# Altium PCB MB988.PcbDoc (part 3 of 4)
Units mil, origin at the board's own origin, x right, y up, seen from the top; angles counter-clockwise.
Board outline 4505 x 6805 mil, 4 copper layers (TopLayer, VCC, GND, BottomLayer), stack 71.6 mil thick; 546 components, 390 nets, 1907 pads, 809 vias.
Unrouted connection lines stored in the file: 2.
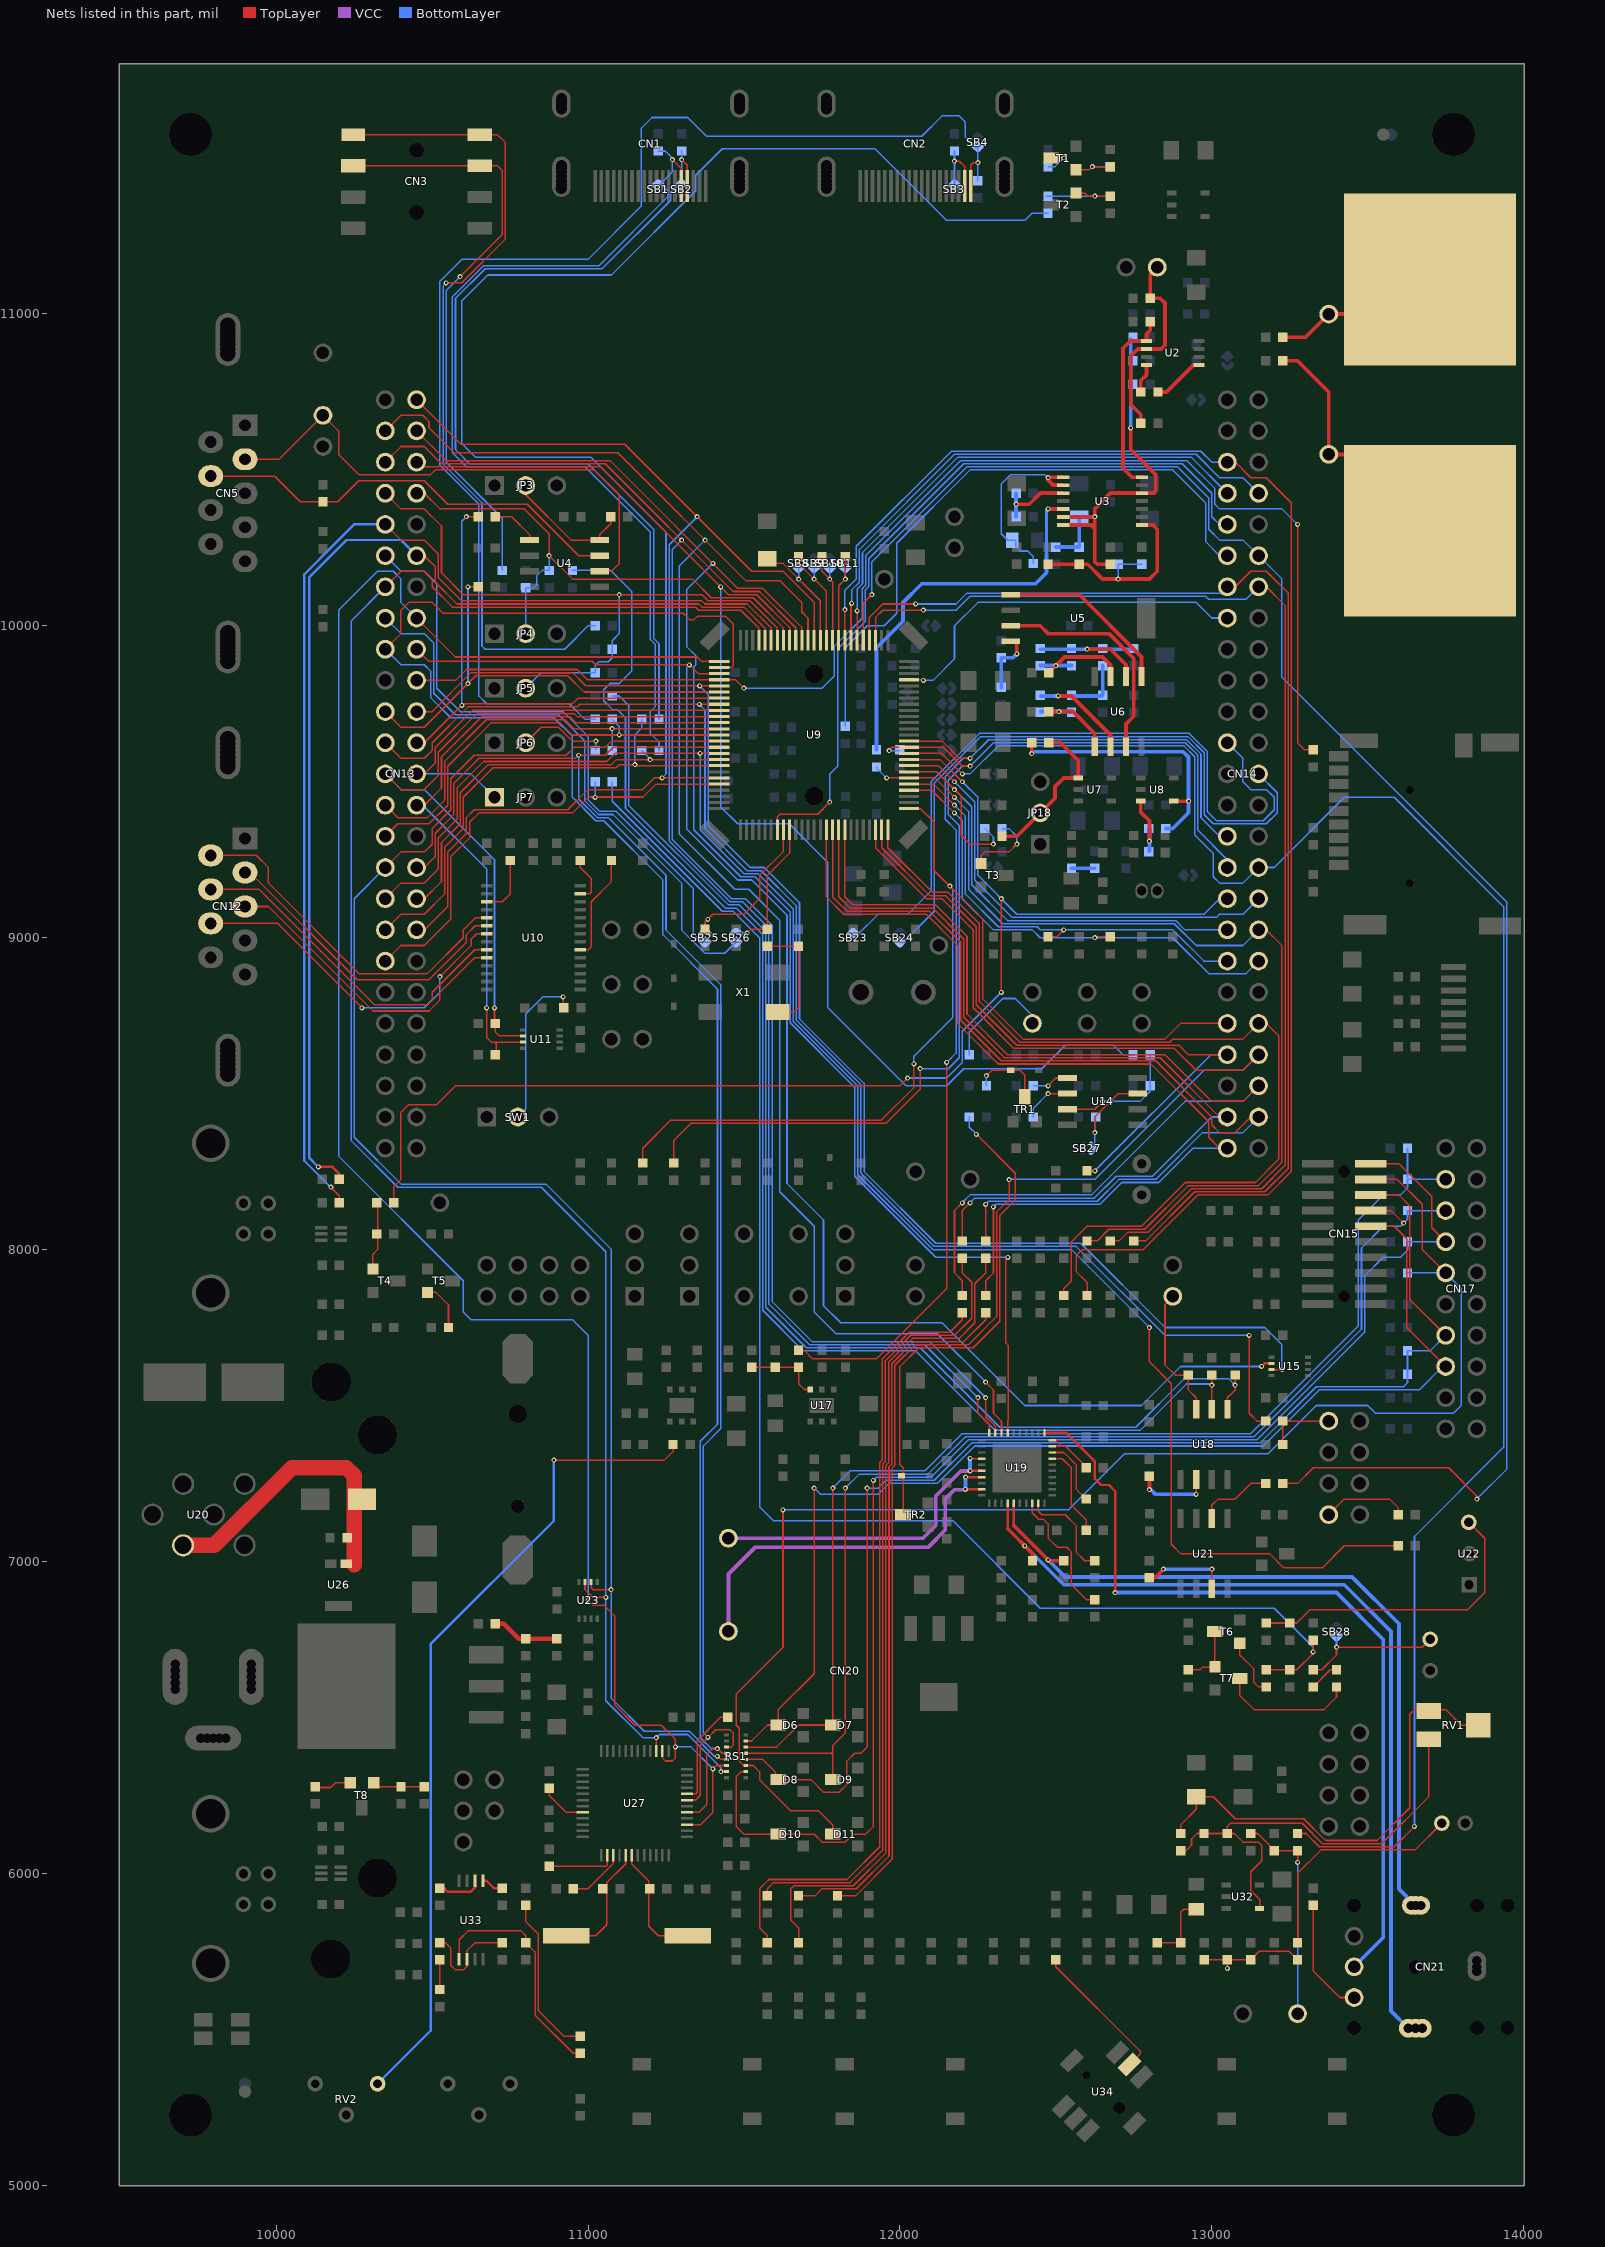
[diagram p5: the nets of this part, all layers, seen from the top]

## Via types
v1: diameter 16, hole 8, TopLayer to BottomLayer, tented both sides, 786 vias
v2: diameter 25, hole 16, TopLayer to BottomLayer, tented both sides, 20 vias
v3: diameter 50, hole 28, TopLayer to BottomLayer, tented both sides, 3 vias

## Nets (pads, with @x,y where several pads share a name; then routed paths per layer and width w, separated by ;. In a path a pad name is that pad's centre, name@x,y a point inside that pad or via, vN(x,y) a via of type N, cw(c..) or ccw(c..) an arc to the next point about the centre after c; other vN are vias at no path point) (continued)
NetR120_2: R120.2 T1.3 | length 101.6
  TopLayer w5: T1.3@12485,11500.5 12524.5,11500.5 v1(12525,11500)
  BottomLayer w5: R120.2@12475,11472.5 12497.5,11472.5 v1(12525,11500)
NetR122_1: R122.1 T6.3 T7.2 | length 202.1
  TopLayer w5: R122.1@12925,6652.5 12962.5,6652.5 12970,6660 13007.5,6660 T7.2@13010,6662.5 T6.3@13010,6775.5
NetR123_2: R123.2 T6.2 | length 189.9
  TopLayer w5: T6.2@13090,6737.5 13090,6700 13135,6655 13135,6612.5 13150,6597.5 R123.2@13175,6597.5
NetR125_1: R125.1 T7.3 | length 432.2
  TopLayer w5: T7.3@13090,6624.5 13090,6570 13135,6525 13360,6525 13400,6565 R125.1@13400,6597.5
NetR125_2: R125.2 R240.1 | length 97.8
  TopLayer w5: R240.1@13325,6597.5 13380,6652.5 R125.2@13400,6652.5
NetR128_1: R128.1 T8.1 | length 116.2
  TopLayer w5: R128.1@10127.5,6275 10175,6275 10190,6290 T8.1@10237.5,6290
NetR129_1: R129.1 U21.6 | length 244
  TopLayer w5: U21.6@13000,7137.5 13000,7180 13020,7200 13075,7200 13125,7250 R129.1@13172.5,7250
NetR131_2: R131.2 R132.1 T8.2 | length 162.5
  TopLayer w5: T8.2@10312.5,6277.5 R132.1@10475,6277.5
NetR137_2: R137.2 U27.2 | length 219.3
  TopLayer w5: R137.2@10875,6022.5 11057.5,6022.5 11061.42,6026.42 U27.2@11061.42,6057.68
NetR139_1: CN1.15 R139.1 R173.1 SB1.1 | length 3087.5
  TopLayer w5: v1(11270,11495) 11298.43,11466.57 CN1.15@11298.43,11410
  BottomLayer w5: R173.1@11225,11522.5 11247.5,11522.5 11270,11500 11270,11455 SB1.1@11233,11418 11255,11396 11255,11375 11035,11155 10665,11155 10565,11055 10565,10555 10610,10510 10990,10510 11200,10300 11200,9955.86 11215,9940.86 11215,9740 11200,9725 11200,9655 11227.5,9627.5 R139.1@11227.5,9600
NetR140_1: C72.1 R140.1 R141.2 RV1.1 U32.4 | length 1457
  TopLayer w5: R140.1@12900,6072.5 12917.5,6072.5 12935,6090 12935,6110 12952.5,6127.5 R141.2@12975,6127.5 ; R141.2@12977.5,6127.5 13072.5,6127.5 13100,6100 13150,6100 13160,6090 13160,6040 13125,6005 13125,5945 13153.15,5916.85 U32.4@13153.15,5887.6 ; C72.1@13050,6127.5 13050,6150 13060,6160 13290,6160 13355,6095 13545,6095 13696.26,6246.26 RV1.1@13696.26,6404.72
NetR140_2: C71.1 R140.2 RV1.2 RV1.3 | length 1470.4
  TopLayer w5: R140.2@12900,6127.5 12900,6155 12950,6205 C71.1@12950,6245 13005,6245 13075,6175 13295,6175 13365,6105 13530,6105 13635,6210 13635,6510 13650,6525 13750,6525 13800,6475 RV1.2@13853.74,6475
NetR144_1: LD5.2 R144.1 | length 523.2
  TopLayer w5: R144.1@10800,5897.5 10800,5845 10840,5805 10840,5560 10922.5,5477.5 LD5.2@10975,5477.5
NetR145_2: R145.2 U27.3 | length 188.8
  TopLayer w5: R145.2@10952.5,5950 11000,5950 11081.1,6031.1 U27.3@11081.1,6057.68
NetR146_1: R77.2 R146.1 | length 2554.3
  TopLayer w5: R146.1@11575,5927.5 11575,5950 11595,5970 11840,5970 11945,6075 11945,7312.22 11953.64,7320.86 11953.64,7643.64 12035,7725 12175,7725 12230,7780 12230,7895 12200,7925 R77.2@12200,7972.5
NetR147_1: R88.2 R147.1 | length 2307.4
  TopLayer w5: R147.1@11675,5927.5 11727.5,5927.5 11750,5950 11860,5950 11965,6055 11965,7303.93 11973.64,7312.57 11973.64,7633.64 12045,7705 12205,7705 12275,7775 R88.2@12275,7797.5
NetR148_1: CN1.16 R148.1 R172.1 SB2.1 | length 2927.5
  TopLayer w5: v1(11300,11495) 11318.11,11476.89 CN1.16@11318.11,11410
  BottomLayer w5: R148.1@11227.5,9700 11227.5,9942.5 11210,9960 11210,10310 11000,10520 10620,10520 10575,10565 10575,11050 10670,11145 11045,11145 11265,11365 11265,11391 SB2.1@11292,11418 ; SB2.1@11300,11415 R172.1@11300,11522.5
NetR156_1: R87.2 R156.1 | length 2522.2
  TopLayer w5: R156.1@11575,5777.5 11575,5800 11550,5825 11550,5950 11580,5980 11830,5980 11935,6085 11935,7316.36 11943.64,7325 11943.64,7648.64 12030,7735 12160,7735 12200,7775 R87.2@12200,7797.5
NetR157_1: R78.2 R157.1 | length 2663.4
  TopLayer w5: R157.1@11675,5777.5 11675,5825 11650,5850 11650,5950 11660,5960 11850,5960 11955,6065 11955,7308.07 11963.64,7316.72 11963.64,7638.64 12040,7715 12190,7715 12240,7765 12240,7890 12275,7925 R78.2@12275,7972.5
NetR159_1: R2.1 R159.1 T2.1 | length 271.6
  TopLayer w5: T2.1@12565,11387.5 12592.5,11387.5 12602.5,11377.5 R2.1@12675,11377.5
  BottomLayer w5: R159.1@12467.5,11377.5 v1(12625,11377.5)
NetR162_2: R162.2 U34.5 | length 462
  TopLayer w5: R162.2@12500,5722.5 12500,5700 12770,5430 12770,5420 U34.5@12736.3,5386.3
NetR163_1: CN20.1 R110.1 R163.1 | length 222.5
  TopLayer w5: R110.1@13227.5,7375 R163.1@13227.5,7450 CN20.1@13375,7450
NetR165_1: C89.1 C135.1 R164.1 R165.1 | length 350
  TopLayer w5: C89.1@12975.28,5722.44 13124.94,5722.44 13152.5,5750 13247.5,5750 R165.1@13275,5722.5 ; v1(13050,5695) R164.1@13050,5722.5
NetR166_2: CN21.6 R166.2 | length 377.4
  TopLayer w5: R166.2@13325,5897.5 13325,5686.57 13410,5601.57 CN21.6@13456.3,5601.57
NetR171_2: C81.1 R170.1 R171.2 | length 226.6
  TopLayer w5: R171.2@12825,5777.5 R170.1@12900,5777.5 12900,5875 12910,5885 C81.1@12950,5885
NetR176_2: R1.2 R176.2 T1.2 | length 171.6
  TopLayer w5: T1.2@12565,11462.5 12607.5,11462.5 v1(12617.5,11472.5) R1.2@12675,11472.5
  BottomLayer w5: v1(12617.5,11472.5) R176.2@12675,11472.5
NetR178_1: C94.1 C97.2 R18.1 R177.1 R178.1 R180.1 R188.2 U3.5 U3.13 U3.14 | length 1409.7
  TopLayer w5: 12623.23,10323.23 12625,10325 ; v1@12623.82,10348.82 v1(12625,10350)
  TopLayer w12: U3.14@12524.02,10323.23 12623.23,10323.23 ; U3.13@12524.02,10348.82 v1@12623.82,10348.82 ; 12610,10323.23 12611.77,10323.23 12625,10310 ; R18.1@12675,10197.5 12632.5,10197.5 12625,10205 12625,10375 12675.59,10425.59 12815.59,10425.59 12820,10430 12820,10485 12740,10565 v1(12740,10635)
  BottomLayer w12: R188.2@12500,10252.5 12574.65,10252.5 C97.2@12574.72,10252.44 C94.1@12574.72,10344.72 ; C94.1@12570,10350 v1(12625,10350) ; v1(12740,10635) R177.1@12740,10920
NetR181_1: C92.2 R181.1 U3.10 | length 241.3
  TopLayer w12: v1(12372.5,10390) 12415,10390 12450.59,10425.59 U3.10@12524.02,10425.59
  BottomLayer w12: R181.1@12372.5,10350 C92.2@12372.5,10425
NetR182_1: JP3.2 R182.1 U4.8 | length 417.1
  TopLayer w5: JP3.2@10800,10450 10800,10420 10945,10275 U4.8@11037.5,10275 11037.5,10292.5 11072.5,10327.5 R182.1@11072.5,10350
NetR185_2: CN3.2 R185.2 | length 1915.3
  TopLayer w5: CN3.2@10247.5,11475 10710,11475 10725,11460 10725,11255 v1(10590,11120)
  BottomLayer w5: v1(10590,11120) 10545,11075 10545,10525 10725,10345 R185.2@10725,10177.5
NetR190_2: CN3.1 R190.2 | length 2674.5
  TopLayer w5: CN3.1@10247.5,11575 10710,11575 10735,11550 10735,11240 10595,11100 v1(10545,11100)
  BottomLayer w5: v1(10545,11100) 10535,11090 10535,10519.14 10660,10394.14 10660,9935 10670,9925 10925,9925 11000,10000 R190.2@11022.5,10000
NetR193_2: C101.2 R21.2 R193.2 U6.7 | length 366.1
  TopLayer w12: R21.2@12477.5,9850 12527.5,9900 12650,9900 12675,9875 U6.7@12675,9837.5
  BottomLayer w12: C101.2@12450,9872.5 R193.2@12550,9872.5
  other v1: 12500,9872.5
NetR194_1: C101.1 R193.1 R194.1 R198.1 U6.6 | length 480.7
  TopLayer w12: v1(12600,9925) 12675,9925 12725,9875 U6.6@12725,9837.5
  BottomLayer w12: C101.1@12450,9925 R198.1@12747.5,9925
NetR194_2: C104.1 R194.2 R200.1 R205.2 U6.2 | length 546.8
  TopLayer w12: v1(12507.5,9775) 12550,9775 12675,9650 U6.2@12675,9612.5
  BottomLayer w12: C104.1@12452.5,9775 R205.2@12647.5,9775 ; R205.2@12650,9777.5 R194.2@12650,9872.5
NetR197_2: R196.2 R197.2 U5.1 | length 190.2
  TopLayer w12: v1(12375,9910) U5.1@12375,9950
  BottomLayer w12: R197.2@12325,9802.5 R196.2@12325,9897.5 12362.5,9897.5 v1(12375,9910)
NetR199_2: JP6.2 R199.2 | length 291.9
  TopLayer w5: JP6.2@10800,9625 10850,9675 10905,9675 10950,9630 v1(11025,9630)
  BottomLayer w5: R199.2@11025,9602.5 v1(11025,9630)
NetR200_2: C104.2 R23.2 R200.2 U6.1 | length 314
  TopLayer w12: R23.2@12477.5,9725 12555,9725 12625,9655 U6.1@12625,9612.5
  BottomLayer w12: C104.2@12452.5,9725 R200.2@12547.5,9725
  other v1: 12510,9725
NetR203_1: CN14.11 R203.1 | length 2032.5
  BottomLayer w5: R203.1@11825,9677.5 11825,9930 11895,10000 11950,10000 11990,10040 11990,10265 12225,10500 12875,10500 12980,10395 12980,10270 13025,10225 CN14.11@13050,10225
NetR204_2: R33.1 R204.2 U8.4 | length 867.3
  TopLayer w12: v1(12422.5,9590) R33.1@12422.5,9625 ; U8.4@12878.15,9437.6 v1(12925.4,9437.6)
  BottomLayer w12: v1(12422.5,9590) 12429,9596.5 12907.91,9596.5 12925,9579.41 v1@12925,9437.6 ; R204.2@12852.5,9350 12875,9350 12925.4,9400.4 v1(12925.4,9437.6)
NetR208_2: R204.1 R208.2 U8.3 | length 209.3
  TopLayer w12: U8.3@12771.85,9437.6 12771.85,9403.15 12800,9375 v1(12800,9310)
  BottomLayer w12: R208.2@12800,9277.5 R204.1@12800,9347.5
NetR209_2: R207.1 R209.2 | length 75
  BottomLayer w12: R207.1@12550,9222.5 R209.2@12625,9222.5
NetR211_2: R211.2 U10.20 | length 343.3
  TopLayer w5: U10.20@10974.61,8961.61 11001.61,8961.61 11010,8970 11010,9115 11075,9180 R211.2@11075,9247.5
NetR212_2: CN9.2 R212.2 | length 370.8
  BottomLayer w5: R212.2@12222.5,8625 12222.5,8697.5 12330,8805 12370,8805 12425,8750 CN9.2@12425,8725 CN9.2@12427.5,8722.5
NetR215_1: R214.1 R215.1 U14.3 | length 406.3
  TopLayer w5: U14.3@12537.5,8450 12625,8450 v1(12650,8475)
  BottomLayer w5: v1(12650,8475) 12770,8475 12802.5,8507.5 R215.1@12802.5,8625
NetR216_2: R216.2 SW1.2 | length 519.2
  TopLayer w5: v1(10920,8810) 10920,8777.5 R216.2@10922.5,8775
  BottomLayer w5: SW1.2@10775,8425 10800,8450 10800,8755 10855,8810 v1(10920,8810)
NetR217_2: D3.2 R217.2 TR1.3 | length 238.7
  TopLayer w5: v1(12277.5,8557.5) 12295,8575 12385,8575 12400.5,8559.5 TR1.3@12400.5,8490
  BottomLayer w5: R217.2@12277.5,8525 v1(12277.5,8557.5)
NetR218_2: R218.2 U14.1 | length 120.4
  TopLayer w5: v1(12475,8525) 12500,8550 U14.1@12537.5,8550
  BottomLayer w5: R218.2@12427.5,8525 v1(12475,8525)
NetR220_2: D5.2 R220.2 TR2.3 | length 1595.5
  TopLayer w5: TR2.3@12010,7150.5 12010,7300 12000,7310 12000,7625 12060,7685 12235,7685 12320,7770 12320,8109.14 12370,8159.14 12370,8245 v1(12245.5,8369.5)
  BottomLayer w5: R220.2@12222.5,8425 12222.5,8392.5 v1(12245.5,8369.5)
NetR222_2: R222.2 U14.2 | length 157.2
  TopLayer w5: v1(12475,8500) U14.2@12537.5,8500
  BottomLayer w5: R222.2@12427.5,8425 12427.5,8452.5 v1(12475,8500)
NetR235_2: R235.2 U18.2 | length 261.2
  TopLayer w5: v1(12950,7215) U18.2@12950,7277.5
  TopLayer w12: v1(12800,7230) R235.2@12800,7272.5
  BottomLayer w12: v1(12800,7230) 12805,7230 12820,7215 v1(12950,7215)
NetR237_2: L4.1 R237.2 R238.2 | length 217.2
  TopLayer w15: L4.1@10702.5,6800 10730,6800 10777.5,6752.5 R237.2@10900,6752.5
NetR240_2: LD10.2 R240.2 SB28.2 | length 467
  TopLayer w5: R240.2@13325,6652.5 13352.5,6652.5 13400,6700 v1(13400,6725) 13675,6725 LD10.2@13700,6750
  BottomLayer w5: v1(13400,6725) SB28.2@13400,6762
NetR242_1: R242.1 U33.6 | length 145.2
  TopLayer w8: R242.1@10525,5952.5 10537.5,5952.5 10550,5940 10622.8,5940 10637.8,5955 U33.6@10637.8,5975.98
NetR243_1: R243.1 U33.5 | length 71.3
  TopLayer w8: U33.5@10663.39,5975.98 10674.02,5975.98 10697.5,5952.5 R243.1@10725,5952.5
NetR244_1: R244.1 R246.2 U33.2 | length 334
  TopLayer w5: R246.2@10525,5777.5 10542.5,5777.5 10560,5760 10560,5705 10575,5690 10600,5690 10612.21,5702.21 10612.21,5752.21 10637.21,5777.21 10724.71,5777.21 R244.1@10725,5777.5
NetR246_1: R160.2 R246.1 | length 95
  TopLayer w5: R160.2@10525,5627.5 R246.1@10525,5722.5
NetR247_1: CN20.7 R247.1 | length 277.1
  TopLayer w5: CN20.7@13375,7150 13425,7200 13570,7200 13597.5,7172.5 R247.1@13597.5,7150
NetR248_1: R248.1 U4.1 | length 151.3
  TopLayer w5: R248.1@10702.5,10350 10755,10350 10812.5,10292.5 U4.1@10812.5,10275
NetR249_1: R119.2 R123.1 R124.2 R249.1 | length 4731.9
  TopLayer w5: R123.1@13175,6652.5 13272.5,6652.5 13325,6705 R119.2@13325,6747.5
  BottomLayer w5: R249.1@11077.5,9500 11077.5,9437.5 11430,9085 11465,9085 11550,9000 11550,7175 11595,7130 12170,7130 12450,6850 13200,6850 13325,6725 v1(13325,6710)
NetRS1_4: CN15.10 CN17.15 D6.3 RS1.4 | length 3718.8
  TopLayer w5: RS1.4@11506,6424.21 11524.21,6424.21 11575.5,6475.5 D6.3@11610,6475.5 11610,6525 11725,6640 v1(11725,7235) ; CN15.10@13510,8075 13585,8075 13625,8035 13625,7750 CN17.15@13750,7625
  BottomLayer w5: v1(11725,7235) 11745,7215 11930,7215 11965,7250 12120,7250 12240,7370 13165,7370 13345,7550 13665,7550 CN17.15@13740,7625
NetRS1_6: CN17.3 D7.3 R223.2 R224.1 RS1.6 | length 3750.7
  TopLayer w5: RS1.6@11506,6404.53 11604.53,6404.53 11675.5,6475.5 D7.3@11785,6475.5 v1(11785,7235)
  BottomLayer w5: v1(11785,7235) 11840,7290 12080,7290 12200,7410 13125,7410 13470,7755 13470,8095 13550,8175 13605,8175 13627.5,8197.5 R223.2@13627.5,8225 CN17.3@13750,8225 ; R223.2@13627.5,8232.5 R224.1@13627.5,8325
NetRS1_8: CN15.8 CN17.5 D9.3 R225.1 RS1.8 | length 3827.7
  TopLayer w5: RS1.8@11506,6384.84 11784.84,6384.84 ; 11784.68,6380 11779.84,6384.84 11785,6390 ; D9.3@11785,6300.5 11785,6410 11825,6450 v1(11825,7235) ; CN15.8@13510,8125 13575,8125 v1(13615,8085)
  BottomLayer w5: v1(11825,7235) 11870,7280 12090,7280 12210,7400 13135,7400 13480,7745 13480,8005 13550,8075 13605,8075 13627.5,8097.5 R225.1@13627.5,8125 CN17.5@13750,8125
NetRS1_10: CN15.6 CN17.13 D8.3 R230.2 R231.1 RS1.10 | length 4096.5
  TopLayer w5: RS1.10@11506,6365.16 11559.84,6365.16 11600,6325 D8.3@11600,6295 ; D8.3@11610,6300.5 11714.5,6300.5 11755,6260 11805,6260 11830,6285 11830,6360 11855,6385 11875,6385 11895,6405 v1(11895,7235) ; CN15.6@13510,8175 13600,8175 13635,8140 13635,7840 CN17.13@13750,7725
  BottomLayer w5: v1(11895,7235) 11930,7235 11955,7260 12110,7260 12230,7380 13155,7380 13335,7560 13615,7560 13627.5,7572.5 R231.1@13627.5,7675 13700,7675 CN17.13@13750,7725
NetRS1_12: CN15.4 CN17.9 D11.3 R226.2 RS1.12 | length 4652.2
  TopLayer w5: v1(11625,7165) 11625,6725 11475,6575 11475,6475 11485,6465 11485,6360 11499.53,6345.47 11529.53,6345.47 11550,6325 11550,6300 11650,6200 11740,6200 11785,6155 D11.3@11785,6125.5 ; CN15.4@13510,8225 13595,8225 13675,8145 13675,8000 CN17.9@13750,7925
  BottomLayer w5: v1(11625,7165) 12540,7165 12720,7345 13180,7345 13335,7500 13500,7500 13525,7475 13775,7475 13800,7500 13800,7875 CN17.9@13750,7925 R226.2@13627.5,7925
NetRS1_14: CN15.2 CN17.7 D10.3 R227.1 RS1.14 | length 4464.5
  TopLayer w5: RS1.14@11506,6325.79 11490.79,6325.79 11475,6310 11475,6150 11500,6125 11725,6125 11750,6100 11825,6100 11850,6125 11890,6125 11915,6150 v1(11915,7260) ; CN15.2@13510,8275 13600,8275 13705,8170 13705,8070 CN17.7@13750,8025
  BottomLayer w5: v1(11915,7260) 11925,7270 12100,7270 12220,7390 13145,7390 13490,7735 13490,7915 13550,7975 13605,7975 13627.5,7997.5 R227.1@13627.5,8025 CN17.7@13750,8025
NetRV2_1: R107.2 RV2.1 | length 2650.4
  TopLayer w5: v1(10890,7325) 11245,7325 11272.5,7352.5 R107.2@11272.5,7375
  BottomLayer w8: RV2.1@10325,5325 10495,5495 10495,6735 10890,7130 v1(10890,7325)
NetSB3_2: CN2.18 R174.2 SB3.2 | length 206.7
  TopLayer w5: v1(12175,11490) 12190,11490 12207.48,11472.52 CN2.18@12207.48,11410
  BottomLayer w5: SB3.2@12175,11418 R174.2@12175,11522.5
NetSB4_2: CN2.19 R135.2 R175.2 SB4.2 | length 4196.6
  TopLayer w5: CN2.19@12227.17,11410 12227.17,11477.17 12235,11485 v1(12250,11485)
  BottomLayer w5: R135.2@11022.5,9700 10990,9700 10940,9750 10675,9750 10650,9775 10650,10390 10525,10515 10525,11105 10595,11175 11000,11175 11170,11345 11170,11595 11205,11630 11320,11630 11380,11570 12070,11570 12135,11635 12190,11635 12210,11615 12210,11567 12245,11532 SB4.2@12243,11532 ; R175.2@12250,11427.5 SB4.2@12250,11537
NetSB23_2: CN14.23 SB23.2 | length 2356.9
  BottomLayer w5: SB23.2@11865,9010 11929.52,9074.52 12024.52,9074.52 12100,9150 12100,9500 12255,9655 12927.57,9655 12985.46,9597.11 12985.46,9404.54 13015,9375 13165,9375 13200,9410 13200,9450 13175,9475 13125,9475 13100,9500 13100,9575 CN14.23@13050,9625
NetSB24_2: CN14.26 SB24.2 | length 2114.9
  BottomLayer w5: SB24.2@12007,8982 12110,9085 12110,9495.86 12259.14,9645 12923.43,9645 12975.46,9592.97 12975.46,9394.54 13005,9365 13175,9365 13210,9400 13210,9465 CN14.26@13150,9525
NetSB25_2: CN13.11 SB25.2 | length 1932.7
  BottomLayer w5: CN13.11@10350,10225 10400,10175 10475,10175 10515,10135 10515,9800 10590,9725 10920,9725 11000,9645 11000,9442.43 11037.43,9405 11090,9405 11338,9157 11338,9012 SB25.2@11368,8982
NetSB26_2: CN13.15 SB26.2 | length 1880
  BottomLayer w5: CN13.15@10350,10025 10400,9975 10475,9975 10505,9945 10505,9784.14 10574.14,9715 10905,9715 10990,9630 10990,9438.28 11033.28,9395 11080,9395 11300,9175 11300,9025 11375,8950 11438,8950 SB26.2@11475,8987
NetT3_2: R22.1 T3.2 | length 238.4
  TopLayer w5: T3.2@12260,9237.5 12260,9262.5 12272.5,9275 12350,9275 v1(12375,9300)
  BottomLayer w5: R22.1@12327.5,9350 12350,9350 12375,9325 v1(12375,9300)
NetT4_2: R51.1 R65.1 T4.2 | length 216.2
  TopLayer w5: T4.2@10310,7937.5 10310,7985 10325,8000 R51.1@10325,8147.5
NetT5_1: R84.1 T5.1 | length 156.6
  TopLayer w5: T5.1@10485,7862.5 10512.5,7862.5 10552.5,7822.5 R84.1@10552.5,7750
NetTP16_1: C79.1 R136.2 R241.1 TP16.1 | length 696.7
  TopLayer w5: R241.1@13125,6127.5 13147.5,6127.5 13200,6075 C79.1@13200,6072.5 R136.2@13275,6072.5 v1(13275,6035)
  BottomLayer w5: TP16.1@13275,5550 v1(13275,6035)
NetTS1_1: R4.1 TP1.1 TS1.1 | length 453.6
  TopLayer w12: R4.1@13227.5,10925 13300,10925 13375,11000 TS1.1@13650,11000
NetTS2_1: R20.1 TP3.1 TS2.1 | length 624.2
  TopLayer w12: R20.1@13227.5,10850 13275,10850 13375,10750 TP3.1@13375,10549.72 TS2.1@13610,10549.72
NetU2_1: R5.2 U2.1 | length 168.2
  TopLayer w12: R5.2@12827.44,10749.72 12854.72,10749.72 12941.61,10836.61 U2.1@12959.69,10836.61
NetU2_5: C2.1 U2.5 U3.7 | length 609.6
  TopLayer w12: U3.7@12775.98,10476.77 12743.23,10476.77 12715,10505 12715,10890 12738.39,10913.39 U2.5@12790.31,10913.39 12790.31,10935.31 12802.56,10947.56 C2.1@12802.56,10975.28
NetU2_6: JP1.2 R3.2 R6.1 U2.6 | length 651
  TopLayer w12: R6.1@12772.5,10650 12772.5,10677.5 12740,10710 12740,10865 12762.8,10887.8 12837.8,10887.8 12850,10900 12850,11035 12835,11050 R3.2@12802.5,11050 12802.5,11127.5 JP1.2@12825,11150
NetU2_8: R5.1 U2.8 | length 94.3
  TopLayer w12: R5.1@12772.44,10749.72 12772.44,10786.82 12790.31,10804.69 U2.8@12790.31,10836.61
NetU3_1: C98.1 R16.1 R17.1 R184.2 U3.1 | length 692
  TopLayer w12: R16.1@12475,10197.5 12602.5,10197.5 12650,10150 12800,10150 12825,10175 12825,10310 12811.77,10323.23 U3.1@12775.98,10323.23
  BottomLayer w5: v1(12700,10150) C98.1@12700,10197.5 R184.2@12775,10197.5
NetU3_9: C96.2 R183.2 U3.8 U3.9 | length 607.4
  TopLayer w12: U3.9@12524.02,10451.18 12491.18,10451.18 12475,10467.36 v1(12475,10475) 12476.77,10476.77 U3.8@12524.02,10476.77
  BottomLayer w5: R183.2@12427.5,10200 12427.5,10222.5 12410,10240 12385,10240 12372.12,10252.88 12372.12,10274.5 12345.5,10274.5 12325,10295 12325,10455 12355,10485 12465,10485 v1(12475,10475)
NetU3_12: R201.2 U3.12 | length 1263.4
  TopLayer w5: v1(12475,10375) v1@12475.59,10374.41
  TopLayer w12: v1@12475.59,10374.41 U3.12@12524.02,10374.41
  BottomLayer w10: 12470,10230 12470,10370 v1(12475,10375)
  BottomLayer w12: R201.2@11925,9602.5 11925,9930 12010,10015 12010,10075 12070,10135 12435,10135 12470,10170 12470,10230
NetU4_6: CN5.2 JP2.2 U4.6 | length 1713.2
  TopLayer w5: CN5.2@9900,10534 10009,10534 JP2.2@10150,10675 10200,10625 10200,10550 10265,10485 10495,10485 10510,10500 11020,10500 11100,10420 11100,10200 11075,10175 U4.6@11037.5,10175
NetU4_7: CN5.7 R7.1 U4.7 | length 1409
  TopLayer w5: CN5.7@9790,10480 9995,10480 10077.5,10397.5 10197.5,10397.5 10265,10465 10475,10465 10550,10390 10805,10390 10970,10225 U4.7@11037.5,10225
NetU5_2: U5.2 U6.3 | length 731.3
  TopLayer w12: U5.2@12355,10000 12450,10000 12475,9975 12670,9975 12750,9895 12750,9710 12725,9685 U6.3@12725,9612.5
NetU5_4: U5.4 U6.5 | length 565.3
  TopLayer w12: U5.4@12355,10100 12575,10100 12775,9900 U6.5@12775,9837.5
NetU7_1: JP18.2 R33.2 R34.2 U7.1 | length 517.5
  TopLayer w12: R34.2@12327.5,9325 12375,9325 12497.4,9447.4 12497.4,9484.8 12525,9512.4 U7.1@12571.85,9512.4 12571.85,9568.15 12515,9625 R33.2@12477.5,9625
NetU10_3: C15.1 U10.3 | length 192.4
  TopLayer w5: U10.3@10675.39,9115.16 10725,9115.16 10750.28,9140.44 C15.1@10750.28,9247.44
NetU10_5: CN12.6 U10.5 | length 1160.4
  TopLayer w5: CN12.6@9790,9264 9936,9264 9975,9225 9975,9175 10265,8885 10485,8885 10600,9000 10600,9025 10638.98,9063.98 U10.5@10675.39,9063.98
NetU10_6: CN12.2 U10.6 | length 1004.3
  TopLayer w5: CN12.2@9900,9209 9916,9209 10260,8865 10490,8865 10610,8985 10610,9010 10638.39,9038.39 U10.6@10675.39,9038.39
NetU10_7: CN12.8 U10.7 | length 1137.1
  TopLayer w5: CN12.8@9790,9046 10004,9046 v1(10275,8775) ; v1(10525,8875) 10625,8975 10625,8995 10642.8,9012.8 U10.7@10675.39,9012.8
  BottomLayer w5: v1(10275,8775) 10475,8775 10525,8825 v1(10525,8875)
NetU10_9: CN12.7 U10.9 | length 1126.5
  TopLayer w5: CN12.7@9790,9155 9945,9155 10315,8785 10485,8785 10500,8800 10500,8825 10636.61,8961.61 U10.9@10675.39,8961.61
NetU10_10: CN12.3 U10.10 | length 999.6
  TopLayer w5: CN12.3@9900,9100 9975,9100 10310,8765 10490,8765 10525,8800 10525,8825 10636.02,8936.02 U10.10@10675.39,8936.02
NetU10_27: C16.1 U10.27 | length 154
  TopLayer w5: U10.27@10974.61,9140.75 11005.75,9140.75 11010,9145 11010,9190 10975.28,9224.72 C16.1@10975.28,9247.44
NetU14_7: R219.2 SB27.1 U14.7 | length 313.5
  TopLayer w5: v1(12625,8375) 12625,8425 12700,8500 U14.7@12762.5,8500
  BottomLayer w5: SB27.1@12618,8333 12625,8340 R219.2@12625,8422.5 ; R219.2@12627.5,8422.5 R219.2@12627.5,8425
NetU17_3: C30.1 R98.2 R99.1 U17.3 | length 250.7
  TopLayer w5: R99.1@11525,7622.5 C30.1@11600.28,7622.5 ; C30.1@11600.22,7622.5 C30.1@11600.28,7622.44 ; C30.1@11600.28,7619.72 C30.1@11600.28,7622.44 ; U17.3@11712.6,7551.18 11693.82,7551.18 11675,7570 R98.2@11675,7622.5 11674.94,7622.44 C30.1@11600.28,7622.44
NetU18_5: R105.1 R187.1 U18.5 | length 4055
  TopLayer w5: U18.5@13050,7487.5 13050,7525 13075,7550 R105.1@13075,7597.5
  BottomLayer w5: R187.1@11077.5,9775 11100,9775 11130,9745 11130,9425 11450,9105 11485,9105 11570,9020 11570,7815 11700,7685 12065,7685 12320,7430 12755.86,7430 12910.86,7585 13055,7585 v1(13075,7565)
NetU18_6: R104.1 R195.1 U18.6 | length 4591.1
  TopLayer w5: U18.6@13000,7487.5 R104.1@13000,7597.5
  BottomLayer w5: R195.1@10950,10177.5 11072.5,10177.5 11140,10110 11140,9855 11100,9815 11070,9815 11050,9795 11050,9760 11080,9730 11095,9730 11120,9705 11120,9415 11440,9095 11475,9095 11560,9010 11560,7805 11690,7675 12050.86,7675 12305.86,7420 12770,7420 12918.94,7568.94 12996.06,7568.94 v1(13000,7565)
NetU18_7: JP14.1 R101.2 U18.7 | length 439.2
  TopLayer w5: JP14.1@12875,7850 12850,7825 12850,7630 12882.5,7597.5 R101.2@12925,7597.5 12925,7550 12950,7525 U18.7@12950,7487.5
NetU19_4: U19.4 U19.6 U30.1 | length 1034
  TopLayer w5: v1(12225,7330) 12225.47,7329.53 U19.4@12262.01,7329.53
  TopLayer w8: v1(12225,7290.16) U19.6@12262.01,7290.16
  VCC w12: U30.1@11450,7074.61 12074.61,7074.61 12115,7115 12115,7210 12195.16,7290.16 v1(12225,7290.16)
  BottomLayer w12: v1(12225,7290.16) v1(12225,7330)
NetU19_7: U19.7 U19.9 U30.2 | length 1259.2
  TopLayer w5: v1@12210,7230 v1(12210,7231.1)
  TopLayer w8: v1(12210,7231.1) U19.9@12262.01,7231.1 ; v1(12210.47,7270.47) U19.7@12262.01,7270.47
  VCC w12: U30.2@11450,6775.39 11450,6960 11535,7045 12090,7045 12145,7100 12145,7200 12175,7230 v1@12210,7230
  BottomLayer w12: v1(12210,7231.1) 12210.47,7231.57 v1(12210.47,7270.47)
NetU19_14: C55.2 CN21.3 U19.14 | length 2801
  TopLayer w8: 12345.47,7104.53 U19.14@12345.47,7187.01
  TopLayer w12: 12345.47,7104.53 12425,7025 C55.2@12425,7002.5
  BottomLayer w12: v1(12400,7050) 12525,6925 13425,6925 13575,6775 13575,5558.15 CN21.3@13630,5503.15
NetU19_15: C56.2 CN21.2 U19.15 | length 2413.6
  TopLayer w8: 12365.16,7114.84 U19.15@12365.16,7187.01
  TopLayer w12: 12365.16,7114.84 12477.5,7002.5 C56.2@12525,7002.5
  BottomLayer w12: v1(12475,7005) 12530,6950 13450,6950 13600,6800 13600,5950 CN21.2@13653.15,5896.85
NetU19_18: C53.2 U19.18 | length 435.1
  TopLayer w5: U19.18@12424.21,7187.01 12424.21,7155.79 12445,7135 12460,7135 12475,7120 12475,7075 12505,7045 12535,7045 12550,7030 12550,6925 12597.5,6877.5 C53.2@12625,6877.5
NetU19_19: C51.2 U19.19 | length 322.5
  TopLayer w5: U19.19@12443.9,7187.01 12443.9,7161.1 12455,7150 12530,7150 12565,7115 12565,7030 12592.5,7002.5 C51.2@12625,7002.5
NetU19_27: C45.2 U19.27 | length 293.9
  TopLayer w5: U19.27@12487.99,7329.53 12520.47,7329.53 12550,7300 12550,7180 12597.5,7132.5 C45.2@12597.5,7100
NetU19_28: C46.2 U19.28 | length 216.7
  TopLayer w5: U19.28@12487.99,7349.21 12525.79,7349.21 12565,7310 12565,7232.5 C46.2@12597.5,7200
NetU19_29: R109.2 U19.29 U19.30 | length 179.7
  TopLayer w5: U19.29@12487.99,7368.9 12531.1,7368.9 12597.5,7302.5 R109.2@12597.5,7300 ; U19.30@12487.99,7388.58 12500.32,7388.58 12520,7368.9
NetU19_31: CN21.5 U19.31 | length 2672.4
  TopLayer w8: U19.31@12463.58,7412.99 12532.01,7412.99 12625,7320 12625,7265 12645,7245 12670,7245 12690,7225 v1(12690,6900)
  BottomLayer w12: v1(12690,6900) 13400,6900 13550,6750 13550,5793.7 CN21.5@13456.3,5700
NetU21_3: R236.2 U21.3 | length 273.9
  TopLayer w5: U21.3@13000,6912.5 v1(13000,6975)
  TopLayer w12: R236.2@12800,6947.5 12817.5,6947.5 v1(12845,6975)
  BottomLayer w12: v1(12845,6975) v1(13000,6975)
NetU22_3: C54.1 R118.1 U22.3 | length 984
  TopLayer w5: C54.1@13177.5,6802.5 13272.5,6802.5 13315,6845 13820,6845 13875,6900 13875,7074 U22.3@13824,7125
NetU26_3: C47.1 U20.1 U26.3 Z1.2 | length 946.7
  TopLayer w50: U20.1@9701.57,7051.57 9801.57,7051.57 10050,7300 10225,7300 10250,7275 10250,6990
NetU27_20: R126.1 U27.20 | length 328.8
  TopLayer w5: U27.20@11317.32,6254.53 11345,6254.53 11350,6259.53 11350,6425 11425,6500 R126.1@11447.5,6500
NetU27_44: R127.2 U27.44 | length 152.8
  TopLayer w5: R127.2@10875,6272.5 10875,6250 10929.53,6195.47 U27.44@10982.68,6195.47
NetU28_2: R165.2 U28.2 | length 751.6
  TopLayer w5: R165.2@13275,5777.5 13275,6000 13350,6075 13651.97,6075 U28.2@13737.6,6160.63
NetU33_1: LD5.1 R154.2 U33.1 | length 757.1
  TopLayer w5: U33.1@10586.61,5724.02 10586.61,5786.61 10615,5815 10785,5815 10800,5800 R154.2@10800,5777.5 10830,5747.5 10830,5545 10952.5,5422.5 LD5.1@10975,5422.5
NetX1_4: C25.1 R37.1 X1.4 | length 369.6
  TopLayer w5: R37.1@11575,8972.5 C25.1@11675,8972.5 11675,8775 11662.01,8762.01 X1.4@11608.27,8762.01
OSC_IN: C73.2 U27.5 X3.2 | length 392.2
  TopLayer w5: X3.2@10930,5800 11025,5800 11060,5835 11060,5970 11120.47,6030.47 U27.5@11120.47,6057.68
OSC_OUT: C74.2 U27.6 X3.1 | length 387.8
  TopLayer w5: U27.6@11140.16,6057.68 11140.16,6029.84 11195,5975 11195,5830 11225,5800 X3.1@11320,5800
PA0: CN14.44 R150.2 U9.23 | length 5372.1
  TopLayer w5: R150.2@11800,5927.5 11857.5,5927.5 11975,6045 11975,7299.79 11983.64,7308.43 11983.64,7628.64 12050,7695 12220,7695 12310,7785 12310,8120 12350,8160 v1(12350,8224) ; U9.23@11921.85,9345.87 11921.85,9288.15 12085,9125 12135,9125 12235,9025 12235,8775 12365,8645 12880,8645 12950,8575 13100,8575 CN14.44@13150,8625
  BottomLayer w5: v1(12350,8224) 12351,8225 12625,8225 12975,8575 13100,8575 CN14.44@13150,8625
PA1: CN14.43 R62.2 U9.24 | length 2191.4
  TopLayer w5: U9.24@11941.53,9345.87 11941.53,9288.47 12095,9135 12145,9135 12245,9035 12245,8785 12375,8655 12895,8655 12925,8625 CN14.43@13050,8625 ; R62.2@12600,8252.5 v1(12625,8252.5)
  BottomLayer w5: v1(12625,8252.5) 12997.5,8625 CN14.43@13050,8625
PA2: CN14.42 R90.2 U9.25 | length 3109.7
  TopLayer w5: U9.25@11961.22,9345.87 11961.22,9288.78 12105,9145 12155,9145 12255,9045 12255,8795 12385,8665 12865,8665 12875,8675 13100,8675 CN14.42@13150,8725 13175,8725 13215,8685 13215,8290 13140,8215 12915,8215 12775,8075 12600,8075 12550,8025 12550,7900 12525,7875 R90.2@12525,7852.5
PA3: CN14.41 R54.1 U9.26 | length 3287
  TopLayer w5: R54.1@11175,8277.5 11175,8325 11265,8415 11940,8415 12045,8520 v1(12045,8595) ; U9.26@12029.13,9413.78 12066.22,9413.78 12110,9370 12110,9215 12265,9060 12265,8805 12395,8675 12850,8675 12900,8725 CN14.41@13050,8725
  BottomLayer w5: v1(12045,8595) 12045,8620 12170,8745 12170,9155 v1(12160,9165)
PA4: CN14.38 R43.1 U9.29 | length 1578.4
  TopLayer w5: U9.29@12029.13,9472.83 12102.17,9472.83 v1(12175,9400) ; v1(12625,9000) 12627.5,9002.5 R43.1@12675,9002.5
  BottomLayer w5: v1(12175,9400) 12200,9375 12200,9125 12300,9025 12425,9025 12450,9000 12875,9000 12990,8885 13110,8885 CN14.38@13150,8925
PA5: CN14.37 R40.1 U9.30 | length 1461.7
  TopLayer w5: U9.30@12029.13,9492.52 12107.48,9492.52 v1(12175,9425) ; R40.1@12475,9002.5 12502.5,9002.5 v1(12525,9025)
  BottomLayer w5: v1(12175,9425) 12210,9390 12210,9140 12315,9035 12440,9035 12450,9025 12875,9025 12975,8925 CN14.37@13050,8925
PA6: CN14.36 R92.1 R201.1 U9.31 | length 3151.4
  TopLayer w5: v1(11957.2,9512.2) 12112.8,9512.2 v1(12175,9450) ; R92.1@12600,8027.5 12632.5,8027.5 12670,8065 12785,8065 12925,8205 13150,8205 13225,8280 13225,8975 13175,9025 CN14.36@13150,9025
  BottomLayer w5: R201.1@11925,9547.5 11925,9544.41 v1(11957.2,9512.2) ; v1(12175,9450) 12220,9405 12220,9155 12330,9045 12880,9045 12950,8975 13100,8975 CN14.36@13150,9025
PA7: CN14.35 R22.2 U9.32 | length 1709.4
  TopLayer w5: U9.32@12029.13,9531.89 12118.11,9531.89 12196.5,9453.5 12196.5,9328.5 12225,9300 v1(12300,9300)
  BottomLayer w5: v1(12175,9475) 12230,9420 12230,9170 12345,9055 12884.14,9055 12914.14,9025 CN14.35@13050,9025 ; R22.2@12272.5,9350 12300,9322.5 v1(12300,9300)
PA8: CN13.6 R215.2 U9.67 | length 4193.7
  TopLayer w5: CN13.6@10450,10525 10465,10510 11040,10510 11450,10100 11541.26,10100 11646.26,9995 U9.67@11646.26,9954.13
  BottomLayer w5: v1(11425,10125) 11425,9420 11480,9365 11645,9365 11768,9242 11768,8776.71 12019.71,8525 12150,8525 12205,8580 12455,8580 12530,8655 12685,8655 12715,8625 R215.2@12747.5,8625
PA9: CN13.8 JP4.2 R186.1 R189.1 U9.68 | length 1771
  TopLayer w5: CN13.8@10450,10425 10475,10425 10525,10375 10795,10375 10875,10295 v1(10875,10225) 10950,10150 11335,10150 11395,10090 11530,10090 11626.57,9993.43 U9.68@11626.57,9954.13
  BottomLayer w5: CN13.8@10450,10425 CN13.8@10475,10425 ; JP4.2@10800,9975 R189.1@10800,10122.5 10827.5,10122.5 10835,10130 10835,10160 10852.5,10177.5 R186.1@10875,10177.5 v1(10875,10225)
PA10: CN13.7 JP5.2 R191.1 R192.1 U9.69 | length 2105.5
  TopLayer w5: CN13.7@10350,10425 10400,10375 10475,10375 10530,10320 10530,10170 10600,10100 11365,10100 11385,10080 11520,10080 11606.89,9993.11 U9.69@11606.89,9954.13
  BottomLayer w5: JP5.2@10800,9800 10850,9850 R191.1@11022.5,9850 11022.5,9872.5 11035,9885 11065,9885 11077.5,9897.5 11077.5,9952.5 11100,9975 v1(11100,10100)
PA11: CN13.9 R61.1 U9.70 | length 3845.3
  TopLayer w5: v1(10175,8200) 10202.5,8172.5 R61.1@10202.5,8150 ; CN13.9@10350,10325 10400,10275 10475,10275 10520,10230 10520,10155 10595,10080 11365,10080 11375,10070 11510,10070 11587.2,9992.8 U9.70@11587.2,9954.13
  BottomLayer w7.5: v1(10175,8200) 10090,8285 10090,10165 10188.98,10263.98
  BottomLayer w8: 10188.98,10263.98 10250,10325 CN13.9@10350,10325
PA12: CN13.12 R75.1 U9.71 | length 3692.5
  TopLayer w5: CN13.12@10450,10225 10475,10225 10510,10190 10510,10140 10580,10070 11355,10070 11365,10060 11500,10060 11567.52,9992.48 U9.71@11567.52,9954.13
  TopLayer w8: v1(10135,8265) 10180,8265 10202.5,8242.5 R75.1@10202.5,8225
  BottomLayer w7.5: v1(10135,8265) 10106.4,8293.6 10106.4,10156.4 10225,10275 10400,10275 CN13.12@10450,10225
PA13: CN13.13 RS1.13 U9.72 U23.7 U27.27 | length 6213.6
  TopLayer w5: CN13.13@10350,10125 10400,10175 10475,10175 10500,10150 10500,10125 10565,10060 11345,10060 11355,10050 11490,10050 11547.83,9992.17 U9.72@11547.83,9954.13 ; U23.7@10990.16,6934.06 10990.16,6909.84 11015,6885 v1(11056.96,6885) ; U27.27@11218.9,6392.32 v1(11218.9,6435) ; v1(11425.79,6325.79) RS1.13@11444,6325.79
  BottomLayer w5: CN13.13@10350,10125 10240,10015 10240,8350 10390,8200 10850,8200 11056.96,7993.04 11056.96,6553.04 11175,6435 v1(11218.9,6435) 11228.9,6445 11320,6445 11425.79,6339.21 v1(11425.79,6325.79)
PA14: CN13.16 RS1.11 U9.76 U27.15 U27.26 | length 6332.4
  TopLayer w5: CN13.16@10450,10025 10575,9900 11350,9900 11363.78,9886.22 U9.76@11420.87,9886.22 ; v1(11000,6875) 11015,6860 11050,6860 11085,6825 11085,6540 11150,6475 11235,6475 11280,6430 11280,6370 11270,6360 11248.58,6360 11238.58,6370 U27.26@11238.58,6392.32 ; U27.15@11317.32,6156.1 11361.1,6156.1 11400,6195 v1(11400,6335) 11410.47,6345.47 RS1.11@11444,6345.47
  BottomLayer w5: CN13.16@10450,10025 10400,10075 10400,10150 10375,10175 10325,10175 10200,10050 10200,8300 10600,7900 10600,7800 10625,7775 10950,7775 11000,7725 v1(11000,6875) ; v1(11280,6405) 11330,6405 v1(11400,6335)
PA15: CN13.17 RS1.7 U9.77 U27.17 | length 6026.6
  TopLayer w5: CN13.17@10350,9925 10400,9975 10400,10050 10425,10075 10500,10075 10535,10040 11305,10040 11325,10020 11340,10020 11350,10030 11441.36,10030 11465,10006.36 11465,9870 11461.53,9866.53 U9.77@11420.87,9866.53 ; U27.17@11317.32,6195.47 11355.47,6195.47 11380,6220 11380,6380 11400,6400 v1(11415,6400) 11430.16,6384.84 RS1.7@11444,6384.84
  BottomLayer w5: CN13.17@10350,9925 10400,9875 10475,9875 10495,9855 10495,9770 10560,9705 10890,9705 10950,9645 10950,9450 11025,9375 11050,9375 11240,9185 11240,9010 11415,8835 11415,7440 11360,7385 11360,6434.68 11394.68,6400 v1(11415,6400)
PB0: CN14.32 R136.1 U9.35 | length 6091.4
  TopLayer w5: U9.35@12029.13,9590.94 12134.06,9590.94 v1(12200,9525) ; R136.1@13275,6127.5 13302.5,6127.5 13345,6085 13585,6085 v1(13650,6150)
  BottomLayer w5: v1(12200,9525) 12225,9525 12315,9615 12911,9615 12945.46,9580.54 12945.46,9329.54 13005,9270 13005,9195 13025,9175 13100,9175 CN14.32@13150,9225 13200,9225 13425,9450 13585,9450 13936.5,9098.5 13936.5,7366.5 13650,7080 v1(13650,6150)
PB1: C62.2 CN14.31 R52.1 U9.36 | length 3627.3
  TopLayer w5: R52.1@11275,8277.5 11275,8350 11330,8405 11955,8405 12065,8515 v1(12065,8580) ; v1(11965,9600) 11975.63,9610.63 12139.37,9610.63 12200,9550 v1(12225,9550)
  BottomLayer w5: v1(11965,9600) C62.2@11997.28,9600 ; v1(12065,8580) 12155,8580 12190,8615 12190,9360 12155,9395 12155,9505 12200,9550 v1(12225,9550) 12300,9625 12915.15,9625 12955.46,9584.68 12955.46,9344.54 13050,9250 CN14.31@13050,9225
PB2: CN14.29 R98.1 U9.37 | length 3669.1
  TopLayer w5: R98.1@11675,7677.5 11692.5,7677.5 11720,7650 11925,7650 12150,7875 v1(12150,8600) ; U9.37@12029.13,9630.32 12134.68,9630.32 12190,9575 v1(12225,9575)
  BottomLayer w5: v1(12150,8600) 12180,8630 12180,9345 12145,9380 12145,9516.72 12203.28,9575 v1(12225,9575) 12285,9635 12919.29,9635 12965.46,9588.82 12965.46,9384.54 13025,9325 CN14.29@13050,9325
PB3: CN13.31 RS1.9 U9.89 U23.6 | length 5180.7
  TopLayer w5: CN13.31@10350,9225 10400,9275 10475,9275 10500,9300 10500,9350 10560,9410 10560,9510 10635,9585 10930,9585 10955,9610 11055,9610 11075.32,9630.32 U9.89@11420.87,9630.32 ; U23.6@11009.84,6934.06 11009.84,6915.16 11015.82,6909.18 v1(11074.18,6909.18) ; v1(11415,6375) 11424.84,6365.16 RS1.9@11444,6365.16
  BottomLayer w5: CN13.31@10350,9225 10250,9125 10250,8360.36 10400.36,8210 10865,8210 11075,8000 v1@11075,6909.18 ; 11075,6858.35 11075,6560 11180,6455 11325,6455 11405,6375 v1(11415,6375) ; 11075,6859.18 v1@11075,6908.35
PB4: CN13.32 RS1.5 U9.90 U27.19 | length 5023.4
  TopLayer w5: CN13.32@10450,9225 10475,9225 10510,9260 10510,9335 10570,9395 10570,9495 10650,9575 10960,9575 v1(10970,9585) 11055,9585 11080.63,9610.63 U9.90@11420.87,9610.63 ; U27.19@11317.32,6234.84 11345,6234.84 11360,6249.84 11360,6410 v1@11385,6435 ; v1(11384.57,6435.43) 11409.15,6460 11455,6460 11465,6450 11465,6410 11459.53,6404.53 RS1.5@11444,6404.53
  BottomLayer w5: v1(10970,9585) 10970,9444.14 11029.14,9385 11065,9385 11250,9200 11250,9025 11425,8850 11425,7425 11370,7370 11370,6450 v1(11384.57,6435.43)
PB5: CN13.33 R113.1 U9.91 | length 5617.4
  TopLayer w5: CN13.33@10350,9125 10400,9175 10475,9175 10520,9220 10520,9320 10580,9380 10580,9480 10665,9565 11060,9565 11085.94,9590.94 U9.91@11420.87,9590.94 ; v1(12800,7750) 12800,7640 12870,7570 12870,7055 12900,7025 13185,7025 13230,6980 13355,6980 13425,7050 R113.1@13597.5,7050
  BottomLayer w5: v1(11359.06,9590.94) 11359.06,9345.94 11500,9205 11545,9205 11658,9092 11658,8731.14 11865,8524.14 11865,8240 12105,8000 12550,8000 v1(12800,7750)
PB6: CN13.34 R139.2 U9.92 | length 1327.1
  TopLayer w5: CN13.34@10450,9125 10475,9125 10530,9180 10530,9305 10590,9365 10590,9465 10680,9555 11075,9555 11091.26,9571.26 U9.92@11420.87,9571.26
  BottomLayer w5: R139.2@11172.5,9600 11198.74,9573.76 v1(11198.74,9571.26)
PB7: CN13.35 R148.2 U9.93 | length 1592.6
  TopLayer w5: CN13.35@10350,9025 10400,9075 10475,9075 10540,9140 10540,9290 10600,9350 10600,9450 10695,9545 11090,9545 11100,9555 v1(11150,9555) 11153.42,9551.58 U9.93@11420.87,9551.58
  BottomLayer w5: v1(11150,9555) 11150,9650 11172.5,9672.5 R148.2@11172.5,9700
PB8: CN13.36 R159.2 U9.95 | length 5543.5
  TopLayer w5: CN13.36@10450,9025 10475,9025 10550,9100 10550,9275 10610,9335 10610,9385 10635,9410 10935,9410 11000,9475 11175,9475 11212.2,9512.2 U9.95@11420.87,9512.2
  BottomLayer w5: v1(11237.2,9512.2) 11250,9525 11250,10300 11010,10540 10640,10540 10595,10585 10595,11041.72 10678.28,11125 11075,11125 11345,11395 11345,11445 11430,11530 11920,11530 12150,11300 12400,11300 12422.5,11322.5 R159.2@12475,11322.5
PB9: CN13.37 R249.2 U9.96 | length 1502.4
  TopLayer w5: CN13.37@10350,8925 10400,8975 10475,8975 10560,9060 10560,9260 10620,9320 10620,9370 10650,9400 10950,9400 11001.18,9451.18 11176.18,9451.18 11217.52,9492.52 U9.96@11420.87,9492.52
  BottomLayer w5: v1(11022.5,9450) R249.2@11022.5,9500
PB10: CN14.15 U9.47 | length 1208
  TopLayer w5: U9.47@12029.13,9827.17 12072.83,9827.17 v1(12075,9825)
  BottomLayer w5: v1(12075,9825) 12105.86,9825 12175,9894.14 12175,10000 12250,10075 12950,10075 13000,10025 CN14.15@13050,10025
PB14: CN14.14 R81.2 U9.53 | length 3915.1
  TopLayer w5: U9.53@11921.85,9954.13 11921.85,10026.85 11945,10050 v1(12075,10050) ; R81.2@12675,8027.5 12702.5,8027.5 12730,8055 12795,8055 12935,8195 13160,8195 13235,8270 13235,10065 13175,10125 CN14.14@13150,10125
  BottomLayer w5: v1(12075,10050) 12180,10050 12225,10095 12980,10095 12990,10085 13110,10085 CN14.14@13150,10125
PB15: CN14.13 R71.2 U9.54 | length 3922.4
  TopLayer w5: U9.54@11902.16,9954.13 11902.16,10027.16 11945,10070 v1(12050,10070) ; R71.2@12750,8027.5 12787.5,8027.5 12945,8185 13170,8185 13245,8260 13245,10105 13175,10175 13125,10175 CN14.13@13075,10125
  BottomLayer w5: v1(12050,10070) 12180,10070 12215,10105 13030,10105 CN14.13@13050,10125 CN14.13@13055,10125
PC0: CN14.49 R88.1 U9.15 | length 3133
  TopLayer w5: U9.15@11764.37,9345.87 11764.37,9130.63 11820,9075 12085,9075 12185,8975 12185,8725 12315,8595 12805,8595 12990,8410 12990,8360 13025,8325 CN14.49@13050,8325 ; R88.1@12275,7852.5 12275,7900 12300,7925 v1(12300,8137)
  BottomLayer w5: v1(12300,8137) 12308,8145 12641.57,8145 12711.57,8215 12830,8215 12940,8325 CN14.49@13050,8325
PC1: CN14.48 R78.1 U9.16 | length 3184.3
  TopLayer w5: U9.16@11784.05,9345.87 11784.05,9130.95 11830,9085 12095,9085 12195,8985 12195,8735 12325,8605 12820,8605 13000,8425 13000,8400 13025,8375 13075,8375 13125,8425 CN14.48@13150,8425 ; R78.1@12275,8027.5 v1(12275,8145)
  BottomLayer w5: v1(12275,8145) 12285,8155 12632.43,8155 12702.43,8225 12820,8225 12970,8375 13100,8375 CN14.48@13150,8425
PC2: CN14.47 R77.1 U9.17 | length 2971.6
  TopLayer w5: U9.17@11803.74,9345.87 11803.74,9131.26 11840,9095 12105,9095 12205,8995 12205,8745 12335,8615 12835,8615 13025,8425 CN14.47@13050,8425 ; R77.1@12200,8027.5 12200,8125 v1(12225,8150)
  BottomLayer w5: v1(12225,8150) 12240,8165 12623.28,8165 12693.28,8235 12810,8235 13000,8425 CN14.47@13050,8425
PC3: CN14.46 R87.1 U9.18 | length 3403.5
  TopLayer w5: U9.18@11823.42,9345.87 11823.42,9131.58 11850,9105 12115,9105 12215,9005 12215,8755 12345,8625 12850,8625 13000,8475 13100,8475 CN14.46@13150,8525 ; R87.1@12200,7852.5 12200,7900 12175,7925 12175,8125 v1(12200,8150)
  BottomLayer w5: v1(12200,8150) 12225,8175 12614.14,8175 12914.14,8475 13100,8475 CN14.46@13150,8525
PC4: CN14.34 U9.33 | length 1493.7
  TopLayer w5: U9.33@12029.13,9551.58 12123.42,9551.58 v1(12175,9500)
  BottomLayer w5: v1(12175,9500) 12240,9435 12240,9185 12360,9065 13015,9065 13025,9075 13100,9075 CN14.34@13150,9125
PC5: CN14.33 R51.2 U9.34 | length 4136.2
  TopLayer w5: R51.2@10377.5,8150 10377.5,8202.5 10400,8225 10400,8440 10425,8465 10515,8465 10575,8525 12000,8525 v1(12025,8550) ; U9.34@12029.13,9571.26 12128.74,9571.26 v1(12200,9500) ; v1@12324.8,8825.2 v1(12325,8825) v1(12325,9125)
  BottomLayer w5: v1(12025,8550) 12150,8550 12200,8600 12200,8700 v1(12325,8825) ; v1(12200,9500) 12250,9450 12250,9200 12375,9075 12975,9075 13025,9125 CN14.33@13050,9125
PC6: CN13.2 U9.63 U19.40 | length 5304.7
  TopLayer w5: CN13.2@10450,10725 10592.37,10582.63 11117.37,10582.63 11525,10175 11625,10175 11725,10075 U9.63@11725,9954.13 ; v1(12250,7525) 12250,7475 12286.42,7438.58 U19.40@12286.42,7412.99
  BottomLayer w5: v1(11350,10350) 11260,10260 11260,9310 11455,9115 11495,9115 11580,9030 11580,7825 11710,7695 12080,7695 v1(12250,7525)
PC7: CN13.3 U9.64 U19.38 | length 5285.7
  TopLayer w5: CN13.3@10350,10625 10400,10675 10470,10675 10490,10655 10490,10635 10570,10555 11095,10555 11505,10145 11615,10145 11685,10075 11685,10045 11705.31,10024.69 U9.64@11705.31,9954.13 ; v1(12275,7575) 12300,7550 12300,7475 12325.79,7449.21 U19.38@12325.79,7412.99
  BottomLayer w5: v1(11375,10275) 11293,10193 11293,9332 11470,9155 11515,9155 11615,9055 11615,8185 11725,8075 11725,7800 11795,7730 12120,7730 v1(12275,7575)
PC8: CN13.4 U9.65 U19.37 | length 4958.8
  TopLayer w5: CN13.4@10450,10625 10545,10530 11070,10530 11480,10120 11560,10120 11685.63,9994.37 U9.65@11685.63,9954.13 ; U19.37@12345.47,7412.99 12345.47,7450 12347.78,7452.31 12347.78,7692.22 12340,7700 12340,7969 v1(12346,7975)
  BottomLayer w5: v1(11400,10200) 11316,10116 11316,9934 11345,9905 11345,9874.35 11339,9868.35 11339,9346 11490,9195 11535,9195 11648,9082 11648,8727 11855,8520 11855,8235 12115,7975 v1(12346,7975)
  other v1: 12346,7975
PC9: CN13.5 U9.66 U19.39 | length 5167.8
  TopLayer w5: CN13.5@10350,10525 10400,10575 10475,10575 10530,10520 11055,10520 11465,10110 11550,10110 11665.94,9994.06 U9.66@11665.94,9954.13 ; v1(12275,7525) 12275,7464.14 12306.1,7433.04 U19.39@12306.1,7412.99
  BottomLayer w5: v1(11300,10275) 11270,10245 11270,9315 11460,9125 11505,9125 11590,9040 11590,7833.28 11718.28,7705 12095,7705 v1(12275,7525)
PC10: CN13.18 U9.78 U15.2 | length 4894.5
  TopLayer w5: CN13.18@10450,9925 10488.5,9886.5 11013.5,9886.5 11025,9875 v1(11325,9875) 11353.15,9846.85 U9.78@11420.87,9846.85
  TopLayer w8: v1(13160,7625) 13169.84,7634.84 U15.2@13190.94,7634.84
  BottomLayer w5: v1(11325,9875) 11316,9866 11316,9349 11480,9185 11525,9185 11638,9072 11638,8212 11755,8095 11755,7820 11810,7765 12135,7765 12400,7500 12775,7500 12900,7625 v1(13160,7625)
PC11: CN13.20 R24.1 U9.79 | length 4207.2
  TopLayer w5: CN13.20@10450,9825 10575,9825 10610,9860 10965,9860 10997.83,9827.17 11472.83,9827.17 v1(11500,9800) ; v1(13275,10325) 13275,9625 13297.5,9602.5 R24.1@13325,9602.5
  BottomLayer w5: v1(11500,9800) 11750,9800 11790,9840 11790,9935 11879.21,10024.21 11879.21,10119.21 11890,10130 11890,10225 12195,10530 12920,10530 13010,10440 13010,10390 13025,10375 13225,10375 v1(13275,10325)
PC12: CN13.22 U9.80 U15.3 | length 4526.6
  TopLayer w5: CN13.22@10450,9725 10500,9725 10625,9850 10950,9850 10992.52,9807.48 U9.80@11420.87,9807.48 ; U15.3@13190.94,7615.16 13191.1,7615 v1(13225,7615)
  BottomLayer w5: v1(11357.52,9807.48) 11385,9780 11385,9360 11520,9225 11565,9225 11678,9112 11678,8739.43 11885,8532.43 11885,8250 12115,8020 12580,8020 12850,7750 13170,7750 13225,7695 v1(13225,7615)
PC13: CN14.9 U9.7 | length 2463.1
  TopLayer w5: U9.7@11607.76,9345 U9.7@11606.89,9345.87 11606.89,9386.89 11616.13,9396.13 11736.13,9396.13 v1(11775,9435)
  BottomLayer w5: v1(11775,9435) 11775,9525 11800,9550 11800,9925 11889.21,10014.21 11889.21,10115 11900,10125.79 11900,10215 12205,10520 12905,10520 13000,10425 13000,10350 13025,10325 CN14.9@13050,10325
PC14: R36.2 SB25.1 U9.8 | length 517.6
  TopLayer w5: R36.2@11375,9027.5 11375,9050 11400,9075 11500,9075 11550,9125 11550,9200 11626.57,9276.57 U9.8@11626.57,9345.87
  BottomLayer w5: SB25.1@11375,9026 11375,9050 v1(11383.79,9058.79)
PC15: R37.2 SB26.1 U9.9 | length 446.3
  TopLayer w5: v1(11510,9015) 11522.5,9027.5 R37.2@11575,9027.5 11575,9200 11646.26,9271.26 U9.9@11646.26,9345.87
  BottomLayer w5: SB26.1@11483,9018 11486,9015 v1(11510,9015)
PD0: CN13.21 R10.1 U9.81 | length 1524
  TopLayer w5: CN13.21@10350,9725 10400,9675 10475,9675 10640,9840 10935,9840 10987.2,9787.8 U9.81@11420.87,9787.8 ; v1(10615,10125) R10.1@10647.5,10125
  BottomLayer w5: v1(10615,9815) v1(10615,10125)
PD1: CN13.24 R248.2 U9.82 | length 1678.9
  TopLayer w5: CN13.24@10450,9625 10475,9625 10600,9750 10950,9750 10968.11,9768.11 U9.82@11420.87,9768.11 ; v1(10610,10350) R248.2@10647.5,10350
  BottomLayer w5: v1(10595,9745) 10595,10335 v1(10610,10350)
PD2: CN13.23 R163.2 U9.83 | length 4695.8
  TopLayer w5: CN13.23@10350,9625 10400,9575 10475,9575 10500,9600 10500,9625 10615,9740 10965,9740 10973.42,9748.42 U9.83@11420.87,9748.42 ; v1(13120,7725) 13120,7475 13145,7450 R163.2@13172.5,7450
  BottomLayer w5: v1(11356.58,9748.42) 11375,9730 11375,9350 11510,9215 11555,9215 11668,9102 11668,8735.28 11875,8528.28 11875,8245 12110,8010 12565,8010 12850,7725 v1(13120,7725)
PD3: CN13.26 JP7.1 U9.84 | length 1365.6
  TopLayer w5: CN13.26@10450,9525 10475,9525 10510,9560 10510,9610 10628.74,9728.74 U9.84@11420.87,9728.74
  BottomLayer w5: CN13.26@10450,9525 10625,9525 JP7.1@10700,9450
PD4: CN13.25 R46.1 U9.85 U11.2 | length 2363.1
  TopLayer w5: CN13.25@10350,9525 10400,9475 10475,9475 10520,9520 10520,9595 10643.74,9718.74 10955,9718.74 10964.68,9709.06 U9.85@11420.87,9709.06 ; R46.1@10700,8712.5 v1(10700,8775) ; R46.1@10702.5,8725 10702.5,8697.5 10715.16,8684.84 U11.2@10790.94,8684.84
  BottomLayer w5: CN13.25@10350,9525 10400,9475 10475,9475 10700,9250 v1(10700,8775)
PD5: CN13.28 R47.1 U9.86 U11.3 | length 2178.8
  TopLayer w5: CN13.28@10450,9425 10475,9425 10530,9480 10530,9580 10658.74,9708.74 10941.26,9708.74 10960.63,9689.37 U9.86@11420.87,9689.37 ; v1(10675,8775) 10675,8680 10689.84,8665.16 U11.3@10790.94,8665.16 ; 10700,8665.16 10705,8660.16 10710,8665.16 ; R47.1@10705,8627.5 10705,8665.16
  BottomLayer w5: CN13.28@10450,9425 10470,9425 10675,9220 v1(10675,8775)
PD6: CN13.27 R199.1 U9.87 | length 1372.5
  TopLayer w5: CN13.27@10350,9425 10390,9385 10485,9385 10540,9440 10540,9565 10673.74,9698.74 10925,9698.74 10953.74,9670 11254.68,9670 ; 11254.68,9669.68 U9.87@11420.87,9669.68
  BottomLayer w5: R199.1@11077.5,9600 v1(11077.5,9670)
PD7: CN13.29 R135.1 U9.88 | length 1370.1
  TopLayer w5: CN13.29@10350,9325 10390,9365 10490,9365 10550,9425 10550,9550 10688.74,9688.74 10911.26,9688.74 10950,9650 U9.88@11420.87,9650
  BottomLayer w5: R135.1@11077.5,9700 11100,9677.5 v1(11100,9650)
PD8: CN14.12 R129.2 U9.55 | length 5890.6
  TopLayer w5: U9.55@11882.48,9954.13 11882.48,10072.48 v1(11910,10100) ; R129.2@13227.5,7250 13275,7250 13325,7300 13760,7300 13850,7210 v1(13850,7200)
  BottomLayer w5: v1(11910,10100) 11910,10205 12215,10510 12890,10510 12990,10410 12990,10310 13025,10275 13100,10275 13225,10150 13225,9835 13946.5,9113.5 13946.5,7296.5 v1(13850,7200)
PD9: CN14.7 U9.56 | length 1632
  TopLayer w5: U9.56@11862.79,9954.13 v1(11862.79,10047.79)
  BottomLayer w5: v1(11862.79,10047.79) 11862.79,10117.79 11880,10135 11880,10235 12185,10540 12935,10540 CN14.7@13050,10425
PD10: CN14.8 U9.57 | length 1760.1
  TopLayer w5: U9.57@11843.11,9954.13 11843.11,10070 v1(11845,10071.89)
  BottomLayer w5: v1(11845,10071.89) 11845,10115 11870,10140 11870,10245 12175,10550 12950,10550 13025,10475 13100,10475 CN14.8@13150,10425
PD11: CN14.5 R79.2 U9.58 | length 4969.5
  TopLayer w5: U9.58@11823.42,9954.13 v1(11823.42,10051.58) ; R79.2@12600,7852.5 12600,7895 12565,7930 12565,7980 12585,8000 12780,8000 12955,8175 13180,8175 13255,8250 13255,10395 13175,10475 13125,10475 CN14.5@13075,10525
  BottomLayer w5: v1(11823.42,10051.58) 11823.42,10113.42 11860,10150 11860,10255 12165,10560 12965,10560 13000,10525 CN14.5@13050,10525
PD12: R13.1 SB11.2 U9.59 | length 314.2
  TopLayer w5: U9.59@11803.74,9954.13 11803.74,10128.74 v1(11825,10150) R13.1@11825,10222.5
  BottomLayer w5: v1(11825,10150) SB11.2@11825,10187
PD13: R12.1 SB10.2 U9.60 | length 319.5
  TopLayer w5: R12.1@11750,10222.5 11750,10175 11784.05,10140.95 U9.60@11784.05,9954.13
  BottomLayer w5: v1(11775,10150) SB10.2@11775,10187
PD14: R11.1 SB9.2 U9.61 | length 342.4
  TopLayer w5: R11.1@11675,10222.5 11675,10200 11764.37,10110.63 U9.61@11764.37,9954.13
  BottomLayer w5: v1(11725,10150) SB9.2@11725,10187
PD15: C7.2 SB8.2 U9.62 | length 382.4
  TopLayer w5: C7.2@11575,10200 11625,10200 11744.68,10080.32 U9.62@11744.68,9954.13
  BottomLayer w5: v1(11675,10150) SB8.2@11675,10187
